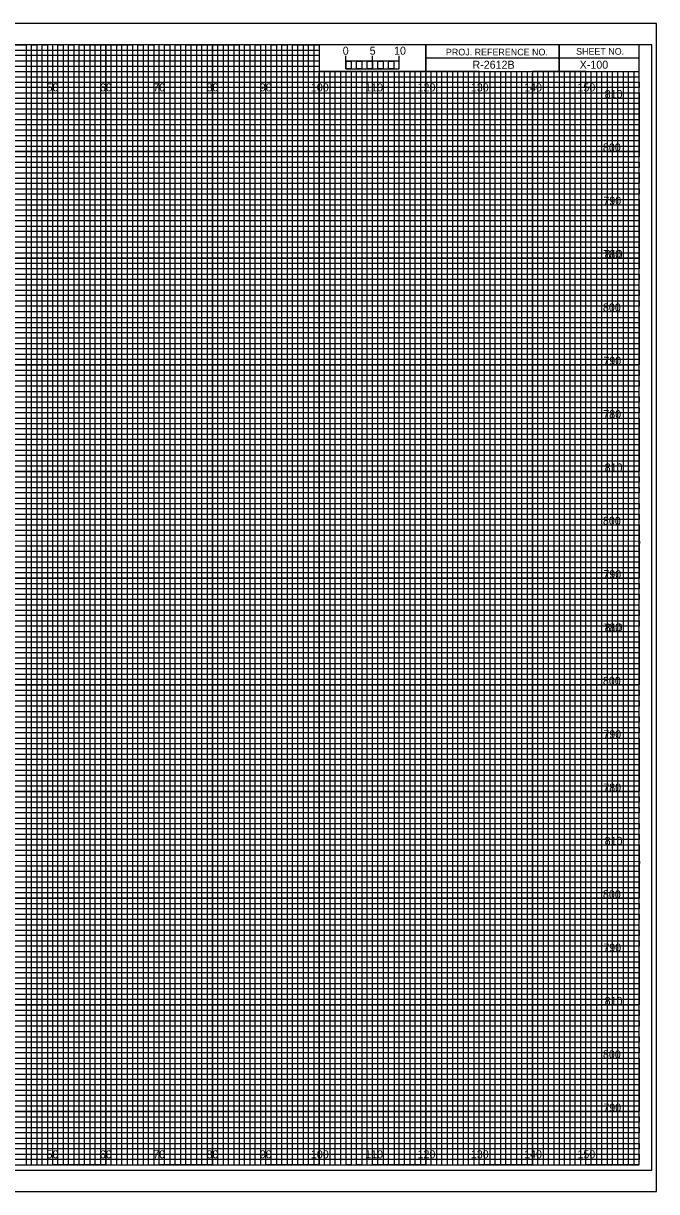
# Model space of a CAD drawing. Extents: x -13 to 323, y -5 to 214.
# Drawn here: x 204.5 to 323.3, y -5 to 214 of the extents above; entities that cross this region are included whole.
import ezdxf

# ---------------------------------------------------------------- set-up
doc = ezdxf.new("R2010")
doc.units = 0
for name, color, linetype in [('Prop XS Bar Scale Labels', 7, 'Continuous'), ('Prop XS Elevation Labels', 7, 'Continuous'), ('Prop XS Offset Labels', 7, 'Continuous'), ('Prop XS Project Number', 7, 'Continuous'), ('Prop XS Sheet Number', 7, 'Continuous'), ('Sheet Cross Section CELL', 7, 'Continuous'), ('Sheet Cross Section Grid Major CELL', 7, 'Continuous'), ('Sheet Cross Section Grid Middle CELL', 7, 'Continuous'), ('Sheet Cross Section Grid Minor 1 CELL', 7, 'Continuous'), ('Sheet Cross Section Grid Minor 2 CELL', 7, 'Continuous'), ('Sheet Cross Section Scale CELL', 7, 'Continuous'), ('Sheet Cutting Line CELL', 7, 'Continuous'), ('Sheet DOT Grid CELL', 7, 'Continuous'), ('Sheet Plot Border Inside CELL', 7, 'Continuous'), ('Sheet Plot Border Outside CELL', 7, 'Continuous')]:
    doc.layers.add(name, color=color, linetype=linetype)

msp = doc.modelspace()

# ---------------------------------------------------------------- linework, layer by layer
at = {"layer": 'Sheet Cross Section CELL'}
for p, q in [((305, 210), (305, 205)), ((305, 205), (305, 210)), ((280, 207.5), (280, 205)), ((320, 207.49), (280, 207.49)), ((280, 205), (320, 205))]:
    msp.add_line(p, q, dxfattribs=at)
for points in [[(320, 210), (0, 210), (0, 0), (320, 0)], [(280, 210), (260, 210), (260, 205.03), (280, 205.03)], [(320, 210), (280, 210), (280, 205), (320, 205)]]:
    msp.add_lwpolyline(points, close=True, dxfattribs=at)
at = {"layer": 'Sheet Cross Section Grid Major CELL'}
for p, q in [((210, 210), (200, 210)), ((210, 0), (210, 210)), ((230, 210), (220, 210)), ((220, 210), (220, 0)), ((230, 0), (230, 210)), ((250, 210), (240, 210)), ((240, 210), (240, 0)), ((250, 0), (250, 210)), ((260, 210), (260, 0)), ((270, 0), (270, 205)), ((290, 205), (280, 205)), ((280, 205), (280, 0)), ((290, 0), (290, 205)), ((310, 205), (300, 205)), ((300, 205), (300, 0)), ((310, 0), (310, 205)), ((220, 0), (210, 0)), ((240, 0), (230, 0)), ((260, 0), (250, 0)), ((280, 0), (270, 0)), ((300, 0), (290, 0)), ((320, 0), (310, 0)), ((320, 0), (320, 0))]:
    msp.add_line(p, q, dxfattribs=at)
for points in [[(0, 200), (320, 200), (320, 190), (0, 190)], [(0, 180), (320, 180), (320, 170), (0, 170)], [(0, 160), (320, 160), (320, 150), (0, 150)], [(0, 140), (320, 140), (320, 130), (0, 130)], [(0, 120), (320, 120), (320, 110), (0, 110)], [(0, 100), (320, 100), (320, 90), (0, 90)], [(0, 80), (320, 80), (320, 70), (0, 70)], [(0, 60), (320, 60), (320, 50), (0, 50)], [(0, 40), (320, 40), (320, 30), (0, 30)], [(0, 20), (320, 20), (320, 10), (0, 10)]]:
    msp.add_lwpolyline(points, dxfattribs=at)
at = {"layer": 'Sheet Cross Section Grid Middle CELL'}
for points in [[(195, 210), (205, 210), (205, 0), (215, 0), (215, 210), (225, 210), (225, 0), (235, 0), (235, 210), (245, 210), (245, 0), (255, 0), (255, 210), (259.93, 210), (260, 210), (260, 205), (264.99, 205), (264.99, 0), (275, 0), (275, 205), (285, 205), (285, 0), (295, 0), (295, 205), (305, 205), (305, 0), (315, 0), (315, 205)], [(0, 205), (275, 205)], [(0, 185), (320, 185), (320, 195), (0, 195)], [(0, 165), (320, 165), (320, 175), (0, 175)], [(0, 145), (320, 145), (320, 155), (0, 155)], [(0, 125), (320, 125), (320, 135), (0, 135)], [(0, 105), (320, 105), (320, 115), (0, 115)], [(0, 85), (320, 85), (320, 95), (0, 95)], [(0, 65), (320, 65), (320, 75), (0, 75)], [(0, 45), (320, 45), (320, 55), (0, 55)], [(0, 25), (320, 25), (320, 35), (0, 35)], [(0, 5), (320, 5), (320, 15), (0, 15)]]:
    msp.add_lwpolyline(points, dxfattribs=at)
at = {"layer": 'Sheet Cross Section Grid Minor 1 CELL'}
for p, q in [((0, 209), (260, 209)), ((260, 209), (260, 207.98)), ((260, 207.98), (0, 207.98)), ((0, 207), (260, 207)), ((260, 205.89), (0, 205.89)), ((260, 207), (260, 205.89)), ((0, 204), (320, 204))]:
    msp.add_line(p, q, dxfattribs=at)
for points in [[(0, 203), (270, 203), (320, 203), (320, 202), (0, 202)], [(0, 201), (320, 201), (320, 199), (0, 199)], [(0, 198), (320, 198), (320, 197), (0, 196.98)], [(0, 196), (320, 196), (320, 194), (0, 194)], [(0, 193), (320, 193), (320, 192), (0, 192)], [(0, 191), (320, 191), (320, 189), (0, 189)], [(0, 188), (320, 188), (320, 187), (0, 187)], [(0, 186), (320, 186), (320, 184), (0, 184)], [(0, 183), (320, 183), (320, 182), (0, 182)], [(0, 181), (320, 181), (320, 179), (0, 179)], [(0, 178), (320, 178), (320, 177), (0, 177)], [(0, 176), (320, 176), (320, 173.95), (320, 173), (320, 172), (0, 172)], [(0, 174), (320, 174), (320, 173), (0, 173)], [(0, 171), (320, 171), (320, 169), (0, 169.03)], [(0, 169.03), (320, 169), (320, 168), (0, 168)], [(0, 167), (320, 167), (320, 166), (0, 166)], [(0, 164), (320, 164), (320, 163), (0, 163)], [(0, 162), (320, 162), (320, 161), (0, 161)], [(-0.07, 158.89), (320, 158.89), (320, 157.88), (-0.07, 157.88)], [(0, 157), (320, 157), (320, 156), (0, 156)], [(0, 154), (320, 154), (320, 153), (0, 153)], [(0, 152), (320, 152), (320, 151), (0, 151)], [(0, 149), (320, 149), (320, 148), (0, 148)], [(0, 147), (320, 147), (320, 146), (0, 146)], [(0, 144), (320, 144), (320, 143), (0, 143)], [(0, 142), (320, 142), (320, 141), (0, 141)], [(0, 139), (320, 139), (319.99, 137.98), (0, 138)], [(0, 137), (320, 137), (320, 136), (0, 136)], [(0, 134), (320, 134), (320, 133), (0, 133)], [(0, 132), (320, 132), (320, 131), (0, 131)], [(0, 129), (320, 129), (320, 128), (0, 128)], [(0, 127), (320, 127), (320, 126), (0, 126)], [(0, 124), (320, 124), (320, 123), (0, 123)], [(0, 122), (320, 122), (320, 121), (0, 121)], [(0, 119), (320, 119), (320, 118), (0, 118)], [(0, 116.99), (320.07, 116.91), (320, 116), (0, 116)], [(0, 114), (320, 114), (320, 113), (0, 113)], [(0, 112), (320, 112), (320, 111), (0, 111)], [(0, 109), (320, 109), (320, 108), (0, 108)], [(0, 107), (320, 107), (320, 106), (0, 106)], [(0, 104), (320, 104), (320, 103), (0, 103)], [(0, 102), (320, 102), (320, 101), (0, 101)], [(0, 99), (320, 99), (320, 98), (0, 98)], [(0, 97), (320, 97), (320, 96), (0, 96)], [(0, 94), (320, 94), (320, 93), (0, 93)], [(0, 92), (320, 92), (320, 91), (0, 91)], [(0, 89), (320, 89), (320, 88), (0, 88)], [(0, 87), (320, 87), (320, 86), (0, 86)], [(0, 84), (320, 84), (320, 83), (0, 83)], [(0, 82), (320, 82), (320, 81), (0, 81)], [(0, 79), (320, 79), (319.99, 77.98), (0, 78)], [(0, 77), (320, 77), (320, 76), (0, 76)], [(0, 74), (320, 74), (320, 73), (0, 73)], [(0, 72), (320, 72), (320, 71), (0, 71)], [(0, 69), (320, 69), (320, 68), (0, 68)], [(0, 67), (320, 67), (320, 66), (0, 66)], [(0, 64), (320, 64), (320, 63), (0, 63)], [(0, 62), (320, 62), (320, 61), (0, 61)], [(0, 59), (320, 59), (320, 58), (0, 58)], [(0, 56.99), (320.07, 56.91), (320, 56), (0, 56)], [(0, 54), (320, 54), (320, 53), (0, 53)], [(0, 52), (320, 52), (320, 51), (0, 51)], [(0, 49), (320, 49), (320, 48), (0, 48)], [(0, 47), (320, 47), (320, 46), (0, 46)], [(0, 44), (320, 44), (320, 43), (0, 43)], [(0, 42), (320, 42), (320, 41), (0, 41)], [(0, 39), (320, 39), (320, 38), (0, 38)], [(0, 37), (320, 37), (320, 36), (0, 36)], [(0, 34), (320, 34), (320, 33), (0, 33)], [(0, 32), (320, 32), (320, 31), (0, 31)], [(0, 29), (320, 29), (320, 28), (0, 28)], [(0, 27), (320, 27), (320, 26), (0, 26)], [(0, 24), (320, 24), (320, 23), (0, 23)], [(0, 22), (320, 22), (320, 21), (0, 21)], [(0, 19), (320, 19), (320, 18), (0, 18)], [(0, 17), (320, 17), (320, 16), (0, 16)], [(0, 14), (320, 14), (320, 13), (0, 13)], [(0, 12), (320, 12), (320, 11), (0, 11)], [(0, 9), (320, 9), (320, 8), (0, 8)], [(0, 7), (320, 7), (320, 6), (0, 6)], [(0, 4), (320, 4), (320, 3), (0, 3)], [(0, 2), (320, 2), (320, 1), (0, 1)]]:
    msp.add_lwpolyline(points, dxfattribs=at)
at = {"layer": 'Sheet Cross Section Grid Minor 2 CELL'}
for p, q in [((267, 205), (266.01, 205)), ((266.01, 205), (266.01, 0)), ((267, 0), (267, 205)), ((269, 205), (268, 205)), ((268, 205), (268, 0)), ((269, 0), (269, 205)), ((266.01, 0), (265, 0)), ((268, 0), (267, 0))]:
    msp.add_line(p, q, dxfattribs=at)
for points in [[(205, 0), (206, 0), (206, 210), (207, 210), (207, 0)], [(207, 0), (208, 0), (208, 210), (209, 210), (209, 0)], [(210, 0), (211, 0), (211, 210), (212, 210), (212, 0)], [(212, 0), (213, 0), (213, 210), (214, 210), (214, 0)], [(215, 0), (216, 0), (216, 210), (217, 210), (217, 0)], [(217, 0), (218, 0), (218, 210), (219, 210), (219, 0)], [(220, 0), (221, 0), (221, 210), (222, 210), (222, 0)], [(222, 0), (223, 0), (223, 210), (224, 210), (224, 0)], [(225, 0), (226, 0), (226, 210), (227, 210), (227, 0)], [(227, 0), (228, 0), (228, 210), (229, 210), (229, 0)], [(230, 0), (231, 0), (231, 210), (232, 210), (232, 0)], [(232, 0), (233, 0), (233, 210), (234, 210), (234, 0)], [(235, 0), (236, 0), (236, 210), (237, 210), (237, 0)], [(237, 0), (238, 0), (238, 210), (239, 210), (239, 0)], [(240, 0), (241, 0), (241, 210), (242, 210), (242, 0)], [(242, 0), (243, 0), (243, 210), (244, 210), (244, 0)], [(245, 0), (246, 0), (246, 210), (247, 210), (247, 0)], [(247, 0), (248, 0), (248, 210), (249, 210), (249, 0)], [(250, 0), (251, 0), (251, 210), (252, 210), (252, 0)], [(252, 0), (253, 0), (253, 210), (254, 210), (254, 0)], [(255, 0), (256, 0), (256, 210), (257, 210), (257, 0)], [(257, 0), (258, 0), (258, 210), (259, 210), (259, 0)], [(260, 0), (261, 0), (261, 205), (262.02, 205), (262.02, 0)], [(262, 0), (263, 0), (263, 205), (263.99, 205), (263.99, 0)], [(270, 0), (270.98, 0), (270.98, 205), (272, 205), (272, 0)], [(272, 0), (273, 0), (273, 205), (274.05, 205), (274.05, 0)], [(275, 0), (276, 0), (276, 205), (277, 205), (277, 0)], [(277, 0), (278, 0), (278, 205), (279, 205), (279, 0)], [(280, 0), (281, 0), (281, 205), (282, 205), (282, 0)], [(282, 0), (283, 0), (283, 205), (284, 205), (284, 0)], [(285, 0), (286, 0), (286, 205), (287, 205), (287, 0)], [(287, 0), (288, 0), (288, 205), (289, 205), (289, 0)], [(290, 0), (291, 0), (291, 205), (292, 205), (292, 0)], [(292, 0), (293, 0), (293, 205), (294, 205), (294, 0)], [(295, 0), (296, 0), (296, 205), (297, 205), (297, 0)], [(297, 0), (298, 0), (298, 205), (299, 205), (299, 0)], [(300, 0), (301, 0), (301, 205), (302, 205), (302, 0)], [(302, 0), (303, 0), (303, 205), (304, 205), (304, 0)], [(305, 0), (306, 0), (306, 205), (307, 205), (307, 0)], [(307, 0), (308, 0), (308, 205), (309, 205), (309, 0)], [(310, 0), (311, 0), (311, 205), (312, 205), (312, 0)], [(312, 0), (313, 0), (313, 205), (314, 205), (314, 0)], [(315, 0), (316, 0), (316, 205), (317, 205), (317, 0)], [(317, 0), (318, 0), (318, 205), (319, 205), (319, 0)]]:
    msp.add_lwpolyline(points, dxfattribs=at)
at = {"layer": 'Sheet Cross Section Scale CELL'}
for p, q in [((265, 205.49), (265, 207.9)), ((265, 206.9), (265, 207.9)), ((270, 205.49), (270, 207.9)), ((275, 205.49), (275, 207.9)), ((275, 206.9), (275, 207.9))]:
    msp.add_line(p, q, dxfattribs=at)
for points in [[(275, 206.9), (265, 206.9), (265, 205.49), (275, 205.49)], [(265, 206.9), (266, 206.9), (266, 205.49), (265, 205.49)], [(267, 206.9), (268, 206.9), (268, 205.49), (267, 205.49)], [(269, 206.9), (270, 206.9), (270, 205.49), (269, 205.49)], [(271, 206.9), (272, 206.9), (272, 205.49), (271, 205.49)], [(273, 206.9), (274, 206.9), (274, 205.49), (273, 205.49)]]:
    msp.add_lwpolyline(points, close=True, dxfattribs=at)
at = {"layer": 'Sheet Cutting Line CELL'}
for p, q in [((323.3, 214), (-13.4, 214)), ((-13.4, -5), (323.3, -5))]:
    msp.add_line(p, q, dxfattribs=at)
at = {"layer": 'Sheet DOT Grid CELL'}
for p, q in [((210, 0), (210, 210)), ((220, 0), (220, 210)), ((230, 0), (230, 210)), ((240, 0), (240, 210)), ((250, 0), (250, 210)), ((260, 0), (260, 204.69)), ((270, 0), (270, 204.69)), ((280, 0), (280, 204.69)), ((290, 0), (290, 204.69)), ((300, 0), (300, 204.69)), ((310, 0), (310, 204.69)), ((0, 200), (320, 200)), ((0, 190), (320, 190)), ((0, 180), (320, 180)), ((0, 170), (320, 170)), ((0, 160), (320, 160)), ((0, 150), (320, 150)), ((0, 140), (320, 140)), ((0, 130), (320, 130)), ((0, 120), (320, 120)), ((0, 110), (320, 110)), ((0, 100), (320, 100)), ((0, 90), (320, 90)), ((0, 80), (320, 80)), ((0, 70), (320, 70)), ((0, 60), (320, 60)), ((0, 50), (320, 50)), ((0, 40), (320, 40)), ((0, 30), (320, 30)), ((0, 20), (320, 20)), ((0, 10), (320, 10))]:
    msp.add_line(p, q, dxfattribs=at)
at = {"layer": 'Sheet Plot Border Inside CELL'}
msp.add_lwpolyline([(-10.8, -1), (322.4, -1), (322.4, 210), (-10.8, 210)], close=True, dxfattribs=at)
at = {"layer": 'Sheet Plot Border Outside CELL'}
msp.add_lwpolyline([(-13.4, -5), (323.3, -5), (323.3, 214), (-13.4, 214)], close=True, dxfattribs=at)

# ---------------------------------------------------------------- texts
at = {"layer": 'Prop XS Bar Scale Labels'}
for s, p in [('5', (269.47, 208.12)), ('10', (274.04, 208.12))]:
    msp.add_text(s, height=1.5, dxfattribs=at).set_placement(p)
at = {"layer": 'Prop XS Elevation Labels'}
for s, p in [('810', (313.55, 200)), ('800', (313.22, 190)), ('790', (313.3, 180)), ('780', (313.28, 170)), ('810', (313.55, 170)), ('800', (313.22, 160)), ('790', (313.3, 150)), ('780', (313.28, 140)), ('810', (313.55, 130)), ('800', (313.22, 120)), ('790', (313.3, 110)), ('780', (313.28, 100)), ('810', (313.55, 100)), ('800', (313.22, 90)), ('790', (313.3, 80)), ('780', (313.28, 70)), ('810', (313.55, 60)), ('800', (313.22, 50)), ('790', (313.3, 40)), ('810', (313.55, 30)), ('800', (313.22, 20)), ('790', (313.3, 10))]:
    msp.add_text(s, height=1.5, dxfattribs=at).set_placement(p)
at = {"layer": 'Prop XS Offset Labels'}
for s, p in [('50', (208.86, 201.25)), ('60', (218.86, 201.25)), ('70', (228.86, 201.25)), ('80', (238.86, 201.25)), ('90', (248.86, 201.25)), ('100', (258.44, 201.25)), ('110', (268.62, 201.25)), ('120', (278.44, 201.25)), ('130', (288.44, 201.25)), ('140', (298.44, 201.25)), ('150', (308.44, 201.25)), ('50', (208.86, 1.25)), ('60', (218.86, 1.25)), ('70', (228.86, 1.25)), ('80', (238.86, 1.25)), ('90', (248.86, 1.25)), ('100', (258.44, 1.25)), ('110', (268.62, 1.25)), ('120', (278.44, 1.25)), ('130', (288.44, 1.25)), ('140', (298.44, 1.25)), ('150', (308.44, 1.25))]:
    msp.add_text(s, height=1.5, dxfattribs=at).set_placement(p)
at = {"layer": 'Prop XS Project Number'}
msp.add_text('R-2612B', height=1.5, dxfattribs=at).set_placement((288.74, 205.5))
at = {"layer": 'Prop XS Sheet Number'}
msp.add_text('X-100', height=1.5, dxfattribs=at).set_placement((308.86, 205.5))
at = {"layer": 'Sheet Cross Section CELL'}
for s, p in [('PROJ. REFERENCE NO.', (283.77, 207.99)), ('SHEET NO.', (308.19, 208.12))]:
    msp.add_text(s, height=1.25, dxfattribs=at).set_placement(p)
at = {"layer": 'Sheet Cross Section Scale CELL'}
msp.add_text('0', height=1.5, dxfattribs=at).set_placement((264.41, 208.12))

doc.saveas('drawing.dxf')
